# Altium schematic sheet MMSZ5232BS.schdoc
size 127 x 101 mm
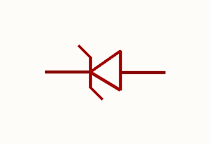
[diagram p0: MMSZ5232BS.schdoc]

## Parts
D?  mmsz5232bs  [SOD-323_L1.7-W1.3-LS2.7-RD-1]  (value not drawn)

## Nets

Not connected (* = marked no-connect by the designer): D? 1 2

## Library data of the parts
D? = mmsz5232bs: 二极管配置:1个独立式;稳压值(标称值):5.6V;稳压值(范围):5.32V~5.88V;耗散功率(Pd):200mW;; Manufacturer: CJ(江苏长电/长晶); AddInBom: yes; ModelId: 6cb9e215dfa74358aef5a433493d9154; ModelTransform: 104.3305,51.181,0,0,0,0,0,0,0; Diode Configuration: 1个独立式; Zener Voltage(Nom): 5.6V; Reverse Leakage Current (Ir): 5uA@3V; Pd - Power Dissipation: 200mW; Impedance(Zzt): 11Ω; Impedance(Zzk): 1.6kΩ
